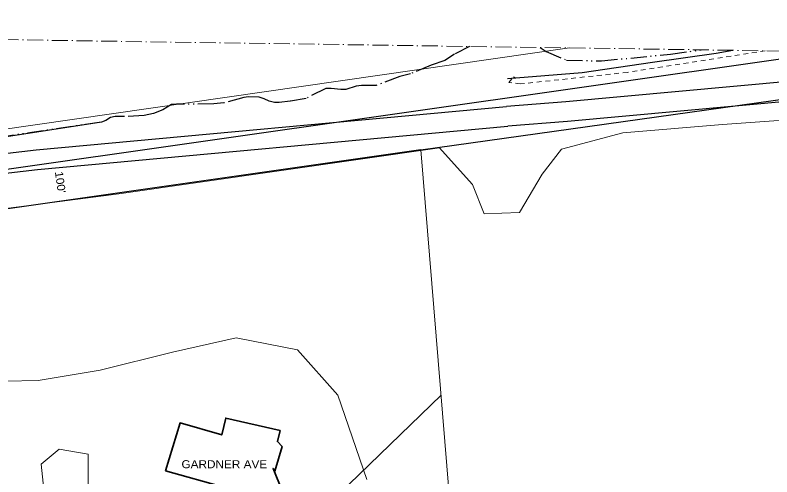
# Model space of a CAD drawing. Extents: x -861682 to -858969, y -1797841 to -1795153.
# Drawn here: x -860350 to -859783, y -1795504 to -1795158 of the extents above; entities that cross this region are included whole.
import ezdxf

# ---------------------------------------------------------------- set-up
doc = ezdxf.new("R2010")
doc.units = 0
doc.header["$LTSCALE"] = 2.4
for name, pattern in [('DASH_DOUBLE_DOT', [9.2, 5, -1.2, 0.3, -1.2, 0.3, -1.2]), ('DOT_DASHED', [7.7, 5, -1.2, 0.3, -1.2]), ('LONG_DASHED', [7.5, 6, -1.5]), ('SHORT_DASHED', [2.7, 1.5, -1.2])]:
    doc.linetypes.add(name, pattern=pattern)
for name, color, linetype, lineweight in [('12', 7, 'Continuous', 35), ('14', 7, 'Continuous', 25), ('16', 7, 'DASH_DOUBLE_DOT', 25), ('18', 7, 'Continuous', 13), ('30', 7, 'Continuous', 13), ('42', 7, 'Continuous', 25), ('46', 7, 'Continuous', 13), ('52', 7, 'LONG_DASHED', 13), ('6', 7, 'Continuous', 25), ('61', 7, 'Continuous', 13)]:
    doc.layers.add(name, color=color, linetype=linetype, lineweight=lineweight)
doc.layers.add('43', color=7, linetype='Continuous')

msp = doc.modelspace()

# ---------------------------------------------------------------- linework, layer by layer
at = {"layer": '12'}
msp.add_lwpolyline([(-860237.284, -1795499.136), (-860192.516, -1795511.505), (-860171.88, -1795547.478), (-860142.478, -1795532.098), (-860156.487, -1795497.249), (-860155.287, -1795499.365), (-860149.778, -1795480.886), (-860153.355, -1795477.136), (-860151.301, -1795468.848), (-860192.025, -1795459.516), (-860194.987, -1795472.065), (-860226.256, -1795463.123)], close=True, dxfattribs=at)
at = {"layer": '14'}
for points in [[(-859980.849, -1795204.899), (-859924.798, -1795200.448), (-859872.15, -1795192.782), (-859824.475, -1795186.064), (-859812.058, -1795183.866), (-859812.057, -1795183.866)], [(-860285.168, -1795237.757), (-860366.345, -1795250.28), (-860460.986, -1795263.158), (-860531.07, -1795274.167)]]:
    msp.add_lwpolyline(points, dxfattribs=at)
at = {"layer": '16'}
for points in [[(-860009.35, -1795180.983), (-860020.491, -1795186.768), (-860027.774, -1795191.557), (-860038.141, -1795194.956), (-860053.444, -1795201.47), (-860061.46, -1795203.43), (-860079.36, -1795210.203), (-860090.228, -1795210.298), (-860094.241, -1795210.805), (-860102.018, -1795213.236), (-860105.798, -1795213.269), (-860113.131, -1795212.388), (-860116.911, -1795212.421), (-860131.733, -1795219.876), (-860143.764, -1795222.108), (-860152.028, -1795222.889), (-860155.572, -1795222.92), (-860159.597, -1795222.01), (-860163.158, -1795220.15), (-860166.948, -1795219.002), (-860174.984, -1795218.836), (-860178.524, -1795219.339), (-860193.376, -1795223.25), (-860200.931, -1795224.025), (-860229.048, -1795224.271), (-860232.59, -1795224.538), (-860239.173, -1795228.376), (-860246.236, -1795231.273), (-860253.076, -1795232.751), (-860267.955, -1795233.59), (-860274.809, -1795233.413), (-860278.347, -1795234.153), (-860281.871, -1795236.547), (-860285.168, -1795237.757), (-860528.26, -1795273.819)], [(-859956.332, -1795181.758), (-859951.862, -1795184.716), (-859936.525, -1795191.241), (-859910.414, -1795191.806), (-859858.578, -1795186.694), (-859835.577, -1795183.522)]]:
    msp.add_lwpolyline(points, dxfattribs=at)
at = {"layer": '18'}
for points in [[(-860031.965, -1795256.805), (-860007.111, -1795284.53), (-859998.226, -1795306.326), (-859971.824, -1795305.466), (-859954.869, -1795276.595), (-859940.292, -1795258.059), (-859894.343, -1795245.833), (-859819.814, -1795239.581), (-859736.012, -1795233.398), (-859631.487, -1795229.196), (-859534.524, -1795216.449), (-859460.922, -1795207.967), (-859360.864, -1795199.506), (-859284.202, -1795191.583), (-859284.171, -1795191.579)], [(-861627.784, -1795676.931), (-861596.674, -1795662.729), (-861531.982, -1795629.555), (-861487.69, -1795614.518), (-861432.082, -1795596.546), (-861364.083, -1795563.344), (-861330.912, -1795546.255), (-861278.234, -1795519.917), (-861241.977, -1795502.494), (-861200.029, -1795489.604), (-861135.894, -1795473.921), (-861059.793, -1795448.445), (-860986.512, -1795424.884), (-860905.443, -1795400.073), (-860827.906, -1795376.712), (-860758.776, -1795364.765), (-860677.115, -1795353.655), (-860512.688, -1795322.681), (-860272.176, -1795291.516), (-860031.805, -1795256.984)], [(-860086.234, -1795505.617), (-860108.054, -1795442.246), (-860138.36, -1795408.249), (-860184.278, -1795399.435), (-860231.917, -1795410.012), (-860286.148, -1795423.482), (-860332.63, -1795431.213), (-860382.242, -1795432.355)]]:
    msp.add_lwpolyline(points, dxfattribs=at)
msp.add_lwpolyline([(-860238.078, -1795570.504), (-860238.356, -1795592.718), (-860253.044, -1795615.531), (-860288.228, -1795618.202), (-860315.024, -1795580.392), (-860327.857, -1795517.886), (-860330.428, -1795494.043), (-860316.821, -1795482.818), (-860295.049, -1795486.645), (-860295.093, -1795508.621), (-860294.922, -1795528.232), (-860280.582, -1795546.774), (-860279.219, -1795567.556), (-860268.066, -1795572.893), (-860264.588, -1795565.301), (-860254.928, -1795562.145), (-860247.373, -1795561.37)], close=True, dxfattribs=at)
at = {"layer": '30'}
for p, q in [((-859934.264, -1795182.08), (-860691.022, -1795290.795)), ((-860045.907, -1795258.409), (-860018.74, -1795586.017)), ((-860237.448, -1795642.208), (-860030.662, -1795442.252))]:
    msp.add_line(p, q, dxfattribs=at)
at = {"layer": '42'}
for p, q in [((-859737.4, -1795184.957), (-860685.181, -1795320.287)), ((-860045.907, -1795258.409), (-859670.829, -1795205.884)), ((-860045.907, -1795258.409), (-860355.24, -1795302.654))]:
    msp.add_line(p, q, dxfattribs=at)
at = {"layer": '52', "linetype": 'SHORT_DASHED'}
msp.add_lwpolyline([(-859787.68, -1795184.222), (-859890.863, -1795200.425), (-859971.251, -1795209.015), (-859979.908, -1795207.998), (-859976.442, -1795203.872), (-859975.185, -1795204.449)], dxfattribs=at)
at = {"layer": '6'}
for points in [[(-859548.549, -1795187.716), (-859632.164, -1795197.063), (-859767.656, -1795207.031), (-859937.124, -1795222.56), (-859981.661, -1795225.976)], [(-859418.729, -1795189.613), (-859511.685, -1795198.483), (-859630.799, -1795211.795), (-859766.438, -1795221.774), (-859935.883, -1795237.301), (-859980.53, -1795240.725)], [(-861626.979, -1795642.068), (-861544.533, -1795599.421), (-861437.181, -1795553.823), (-861360.226, -1795517.943), (-861269.063, -1795485.483), (-861201.703, -1795460.32), (-861135.053, -1795434.926), (-860930.273, -1795370.755), (-860759.796, -1795329.096), (-860655.328, -1795305.026), (-860586.415, -1795295.208), (-860452.636, -1795272.3), (-860334.137, -1795258.505), (-859981.661, -1795225.976)], [(-861627.338, -1795657.588), (-861543.402, -1795614.17), (-861436.05, -1795568.572), (-861359.095, -1795532.692), (-861267.932, -1795500.232), (-861200.572, -1795475.069), (-861133.922, -1795449.675), (-860929.142, -1795385.504), (-860758.665, -1795343.845), (-860654.197, -1795319.775), (-860585.284, -1795309.957), (-860451.505, -1795287.049), (-860333.006, -1795273.254), (-859980.53, -1795240.725)]]:
    msp.add_lwpolyline(points, dxfattribs=at)
at = {"layer": '61', "linetype": 'DOT_DASHED'}
msp.add_line((-861615.801, -1795157.51), (-858974.429, -1795196.105), dxfattribs=at)

# ---------------------------------------------------------------- texts
at = {"layer": '43', "width": 1.1}
msp.add_text("100'", height=6, rotation=278.155, dxfattribs=at).set_placement((-860320.107, -1795275.026))
at = {"layer": '46', "width": 1.1}
msp.add_text('GARDNER AVE', height=6, dxfattribs=at).set_placement((-860225.195, -1795497.078))

doc.saveas('drawing.dxf')
